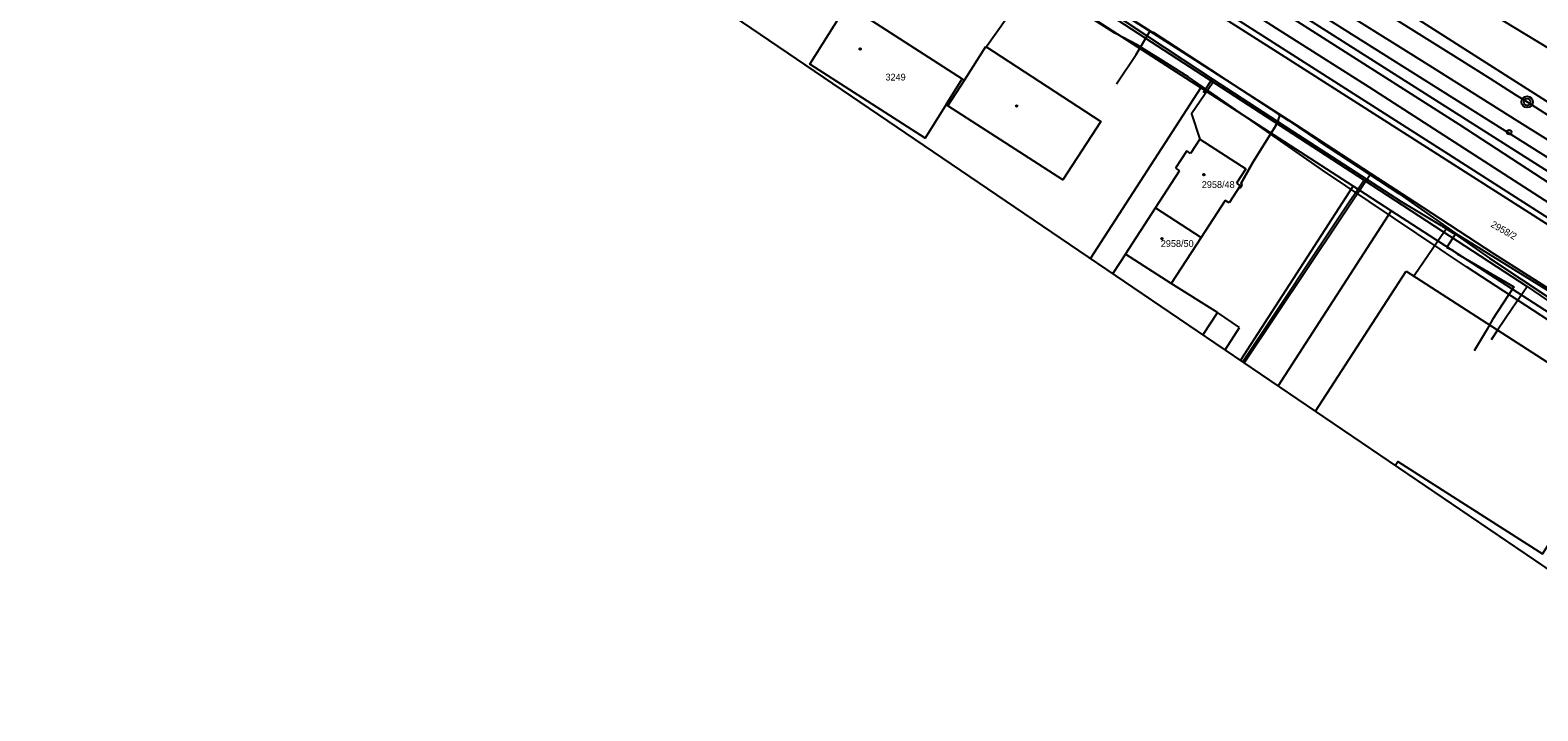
# Model space of a CAD drawing. Extents: x -621145 to -620110, y -1122807 to -1121971.
# Drawn here: x -620961 to -620628.4, y -1122600.4 to -1122450.2 of the extents above; entities that cross this region are included whole.
import ezdxf

# ---------------------------------------------------------------- set-up
doc = ezdxf.new("R2010")
doc.units = 0
for name, color, linetype in [('060601_EOV', 7, 'Continuous'), ('060604_ROZVODY_SEE', 7, 'Continuous'), ('CETIN', 7, 'Continuous'), ('GasNet', 7, 'Continuous'), ('itself', 7, 'Continuous'), ('PS 06-14-01_trasa_sdělovací_nové', 7, 'Continuous'), ('RÁMY', 7, 'Continuous'), ('SEE', 7, 'Continuous'), ('SSZT', 7, 'Continuous'), ('VAS stoka', 7, 'Continuous'), ('VAS vodovod', 7, 'Continuous'), ('Vrstva 1', 7, 'Continuous'), ('Vrstva 53', 7, 'Continuous'), ('Vrstva 55', 7, 'Continuous'), ('Vrstva 56', 7, 'Continuous'), ('Vrstva 57', 7, 'Continuous'), ('Vrstva 62', 7, 'Continuous'), ('Vrstva 7', 7, 'Continuous')]:
    doc.layers.add(name, color=color, linetype=linetype)

msp = doc.modelspace()

# ---------------------------------------------------------------- linework, layer by layer
at = {"layer": '060601_EOV'}
msp.add_lwpolyline([(-620599.21, -1122483.22), (-620683.52, -1122429.44), (-620756.33, -1122383.52), (-620765.8, -1122398.39), (-620784.65, -1122386.39), (-620822.22, -1122362.42), (-620817.53, -1122355.08), (-620826.41, -1122348.08), (-620839.92, -1122337.94), (-620848.84, -1122332), (-620848.83, -1122331.99)], dxfattribs=at)
at = {"layer": '060604_ROZVODY_SEE'}
msp.add_lwpolyline([(-620443.53, -1122595), (-620456.11, -1122587.12), (-620447.82, -1122572.96), (-620450.95, -1122571.45), (-620470.59, -1122561.48), (-620499.61, -1122545.57), (-620522.04, -1122531.47), (-620538.89, -1122521.21), (-620599.21, -1122483.22), (-620683.52, -1122429.44), (-620756.33, -1122383.52), (-620765.8, -1122398.39)], dxfattribs=at)
at = {"layer": 'CETIN'}
for points in [[(-620825.92, -1122405.87), (-620824.51, -1122406.99), (-620818.94, -1122399.06), (-620813.77, -1122391.56), (-620811.94, -1122388.94), (-620806.05, -1122392.88), (-620797.93, -1122398.39), (-620788.82, -1122404.57), (-620785.51, -1122405.86), (-620781.04, -1122408.44), (-620779.59, -1122408.85), (-620776.1, -1122410.97), (-620774.86, -1122411.81), (-620766.93, -1122416.76), (-620729.54, -1122440.11), (-620722.4, -1122445), (-620713.88, -1122450.37)], [(-620721.34, -1122462.04), (-620716.98, -1122455.59), (-620713.88, -1122450.37)], [(-620716.98, -1122455.59), (-620713.88, -1122450.37)], [(-620713.88, -1122450.37), (-620713.18, -1122450.73), (-620698.82, -1122460.09), (-620685.49, -1122468.76)], [(-620698.82, -1122460.09), (-620713.18, -1122450.73)], [(-620694.25, -1122484.84), (-620694.04, -1122484.98), (-620693.69, -1122484.45), (-620693.79, -1122484), (-620691.17, -1122479.25), (-620686.25, -1122471.41), (-620685.67, -1122470.12), (-620685.31, -1122469.14), (-620685.49, -1122468.76)], [(-620685.67, -1122470.12), (-620686.25, -1122471.41), (-620691.17, -1122479.25), (-620693.79, -1122484), (-620693.69, -1122484.45)], [(-620685.49, -1122468.76), (-620683.38, -1122470.13), (-620676.74, -1122474.66), (-620659.07, -1122486.24), (-620646.43, -1122495.05)], [(-620648.44, -1122498.16), (-620646.43, -1122495.05)], [(-620648.44, -1122498.16), (-620646.43, -1122495.05)], [(-620646.43, -1122495.05), (-620612.92, -1122515.84), (-620612.23, -1122516.26), (-620607.1, -1122519.79), (-620583.87, -1122535.51), (-620565.48, -1122548.17), (-620561.56, -1122551.58), (-620557.36, -1122556.05), (-620552.9, -1122562.72), (-620546.13, -1122574.35), (-620544.03, -1122578.53)], [(-620648.44, -1122498.16), (-620647.38, -1122498.61), (-620646.14, -1122499.59)], [(-620648.44, -1122498.16), (-620647.38, -1122498.61), (-620646.14, -1122499.59), (-620633.65, -1122506.89), (-620638.34, -1122514.06), (-620639.54, -1122516.17), (-620642.38, -1122521.01)], [(-620646.14, -1122499.59), (-620633.65, -1122506.89)], [(-620633.65, -1122506.89), (-620638.34, -1122514.06)], [(-620638.34, -1122514.06), (-620639.54, -1122516.17), (-620642.38, -1122521.01)]]:
    msp.add_lwpolyline(points, dxfattribs=at)
at = {"layer": 'GasNet'}
for points in [[(-620782.63, -1122409.86), (-620782.01, -1122410.24), (-620780.25, -1122411.07), (-620777.02, -1122412.94), (-620768.84, -1122416.49), (-620765.93, -1122417.88), (-620758.63, -1122422.59), (-620737.62, -1122436.24), (-620727.26, -1122442.97), (-620706.73, -1122456.7), (-620700.22, -1122460.96), (-620682.51, -1122472.52), (-620658.5, -1122488), (-620649.67, -1122493.31), (-620649.45, -1122493.45), (-620648.52, -1122494.04), (-620647.09, -1122494.92), (-620646.9, -1122495.04), (-620639.06, -1122500.54), (-620610.88, -1122519.2)], [(-620700.22, -1122460.96), (-620702.23, -1122464.06)], [(-620648.52, -1122494.04), (-620649.59, -1122495.62), (-620655.51, -1122504.17)], [(-620655.51, -1122504.17), (-620655.67, -1122504.4), (-620655.88, -1122504.7)]]:
    msp.add_lwpolyline(points, dxfattribs=at)
at = {"layer": 'itself'}
msp.add_lwpolyline([(-620616.25, -1122520.59), (-620644.13, -1122502.42), (-620648.74, -1122499.33), (-620649.95, -1122498.54), (-620675.91, -1122481.07), (-620699.14, -1122464.9), (-620705.51, -1122460.51), (-620711.67, -1122456.57), (-620715.75, -1122454.11), (-620716.79, -1122453.45), (-620721.67, -1122450.84), (-620745.77, -1122435.49)], dxfattribs=at)
at = {"layer": 'PS 06-14-01_trasa_sdělovací_nové'}
msp.add_lwpolyline([(-620538.89, -1122521.21), (-620538.89, -1122521.21), (-620599.21, -1122483.22), (-620683.52, -1122429.44), (-620756.33, -1122383.52), (-620761.98, -1122392.4), (-620753.37, -1122398.54), (-620735.26, -1122410.11), (-620735.26, -1122410.11)], dxfattribs=at)
at = {"layer": 'RÁMY'}
for points in [[(-621061.56, -1122093.92), (-620192.94, -1122683.83), (-620276.37, -1122806.68), (-621144.99, -1122216.77)], [(-620887.83, -1122211.9), (-620192.94, -1122683.83), (-620276.37, -1122806.68), (-620971.26, -1122334.75)]]:
    msp.add_lwpolyline(points, close=True, dxfattribs=at)
at = {"layer": 'SEE'}
msp.add_lwpolyline([(-620611.37, -1122497.7), (-620665.57, -1122462.75), (-620686.03, -1122449.83), (-620727.54, -1122423.18), (-620794.51, -1122379.86), (-620815.52, -1122356.95), (-620832.17, -1122344.66), (-620847.81, -1122332.59), (-620908.26, -1122294.69)], dxfattribs=at)
at = {"layer": 'SSZT'}
msp.add_lwpolyline([(-620879.24, -1122313.32), (-620842.99, -1122336.61), (-620835.05, -1122343.25), (-620812.66, -1122358.95), (-620764.9, -1122389.75), (-620688.59, -1122438.97), (-620596.98, -1122496.73), (-620576.74, -1122509.48), (-620506.75, -1122556.12), (-620447.29, -1122593.62), (-620363.27, -1122647.56), (-620313.97, -1122679.22), (-620306.51, -1122669.29), (-620273.14, -1122696.27), (-620258.42, -1122709.14), (-620248.07, -1122696.09)], dxfattribs=at)
at = {"layer": 'VAS stoka'}
msp.add_line((-620693.16, -1122523.62), (-620665.23, -1122481.83), dxfattribs=at)
msp.add_lwpolyline([(-620781.72, -1122408.87), (-620776.69, -1122412.14), (-620774.2, -1122412.02), (-620772.21, -1122412.95), (-620766.77, -1122415.95), (-620758.11, -1122421.89), (-620737.16, -1122435.39), (-620726.71, -1122442.22), (-620705.9, -1122455.54), (-620681.71, -1122471.08), (-620665.23, -1122481.83), (-620655.61, -1122488.12), (-620638.12, -1122499.53), (-620609.99, -1122517.38), (-620585.88, -1122533.44), (-620564.23, -1122548.6), (-620546.83, -1122572.05), (-620541.25, -1122582.33), (-620541.87, -1122584.42), (-620543.53, -1122584.85), (-620544.25, -1122585.03)], dxfattribs=at)
at = {"layer": 'VAS vodovod'}
for points in [[(-620783.05, -1122410.36), (-620779.49, -1122412.44), (-620776.82, -1122413.57), (-620766.15, -1122419), (-620759.23, -1122423.16), (-620738.05, -1122436.88), (-620666.7, -1122483.31), (-620630.69, -1122506.76), (-620611.44, -1122519.95), (-620587.32, -1122536.52), (-620566.14, -1122551.51), (-620558.22, -1122559.71), (-620551.85, -1122569.08), (-620547.83, -1122576.32), (-620546.15, -1122586.98), (-620546.1, -1122587.26)], [(-620738.05, -1122436.88), (-620738.12, -1122437.06), (-620750.23, -1122454.2)], [(-620699.97, -1122461.66), (-620704.79, -1122468.67), (-620702.93, -1122474.27)], [(-620666.7, -1122483.31), (-620668.33, -1122485.75), (-620669.97, -1122488.2), (-620693.49, -1122523.4)], [(-620630.69, -1122506.76), (-620630.78, -1122506.91), (-620634.04, -1122511.65), (-620637.29, -1122516.39), (-620638.69, -1122518.58)]]:
    msp.add_lwpolyline(points, dxfattribs=at)
at = {"layer": 'Vrstva 1'}
for points in [[(-620851.64, -1122327.08), (-620840.38, -1122334.59), (-620831.19, -1122341.26), (-620824.9, -1122346.12), (-620811.35, -1122356.78), (-620800.85, -1122364.55), (-620800.09, -1122365.07), (-620796.17, -1122367.69), (-620795.02, -1122368.44), (-620786.31, -1122373.93), (-620764.42, -1122387.67), (-620747.63, -1122398.19), (-620733.73, -1122406.89), (-620718.35, -1122416.52), (-620703.01, -1122426.15), (-620686.98, -1122436.2), (-620670.85, -1122446.34), (-620652.24, -1122458.03), (-620632.99, -1122470.12), (-620616.99, -1122480.17)], [(-620538.89, -1122521.21), (-620599.21, -1122483.22), (-620683.52, -1122429.44), (-620747.38, -1122389.13), (-620756.33, -1122383.52)], [(-620659.94, -1122447.67), (-620652.83, -1122452.14), (-620645.8, -1122456.55), (-620638.91, -1122460.88), (-620633.12, -1122464.53), (-620630.72, -1122466.04), (-620624.36, -1122470.05)], [(-620659.94, -1122447.67), (-620652.83, -1122452.14), (-620645.8, -1122456.55), (-620638.91, -1122460.88), (-620633.12, -1122464.53), (-620630.72, -1122466.04), (-620624.36, -1122470.05)]]:
    msp.add_lwpolyline(points, dxfattribs=at)
at = {"layer": 'Vrstva 53'}
for p, q in [((-620638.48, -1122446.57), (-620552.09, -1122499.2)), ((-620545.92, -1122532.26), (-620679.51, -1122447.56))]:
    msp.add_line(p, q, dxfattribs=at)
at = {"layer": 'Vrstva 55'}
for p, q in [((-620684.91, -1122455.63), (-620825.92, -1122365.89)), ((-620645.72, -1122471.03), (-620807.67, -1122367.84)), ((-620702.74, -1122462.95), (-620757.34, -1122427.68)), ((-620638.48, -1122446.57), (-620552.09, -1122499.2)), ((-620545.92, -1122532.26), (-620679.51, -1122447.56)), ((-620754.9, -1122461.23), (-620750.13, -1122453.84)), ((-620557.45, -1122536.96), (-620684.91, -1122455.63)), ((-620755.36, -1122460.94), (-620754.9, -1122461.23)), ((-620727.06, -1122500.6), (-620702.74, -1122462.95)), ((-620669.14, -1122484.66), (-620702.74, -1122462.95)), ((-620758.55, -1122466.88), (-620758.93, -1122466.63)), ((-620587.17, -1122509.18), (-620645.72, -1122471.03)), ((-620705.81, -1122476.87), (-620708.28, -1122480.69)), ((-620704.97, -1122477.41), (-620705.81, -1122476.87)), ((-620702.93, -1122474.27), (-620704.97, -1122477.41)), ((-620702.93, -1122474.27), (-620692.81, -1122480.83)), ((-620708.28, -1122480.69), (-620707.44, -1122481.23)), ((-620712.73, -1122489.39), (-620707.44, -1122481.23)), ((-620692.81, -1122480.83), (-620694.86, -1122483.99)), ((-620694.86, -1122483.99), (-620694.01, -1122484.54)), ((-620694.01, -1122484.54), (-620696.48, -1122488.34)), ((-620693.96, -1122523.08), (-620669.14, -1122484.66)), ((-620660.74, -1122490.09), (-620669.14, -1122484.66)), ((-620719.36, -1122499.62), (-620712.73, -1122489.39)), ((-620712.73, -1122489.39), (-620702.63, -1122495.93)), ((-620697.33, -1122487.79), (-620702.63, -1122495.93)), ((-620696.48, -1122488.34), (-620697.33, -1122487.79)), ((-620660.74, -1122490.09), (-620685.68, -1122528.7)), ((-620576.58, -1122544.45), (-620660.74, -1122490.09)), ((-620702.63, -1122495.93), (-620709.28, -1122506.15)), ((-620719.36, -1122499.62), (-620722.14, -1122503.94)), ((-620677.41, -1122534.31), (-620657.43, -1122503.38)), ((-620657.43, -1122503.38), (-620581.67, -1122552.32)), ((-620699.07, -1122512.52), (-620709.28, -1122506.15)), ((-620694.2, -1122515.81), (-620699.07, -1122512.52)), ((-620697.39, -1122520.75), (-620694.2, -1122515.81))]:
    msp.add_line(p, q, dxfattribs=at)
for points in [[(-620758.93, -1122466.63), (-620763.57, -1122474.01), (-620789, -1122457.71), (-620780.78, -1122444.6), (-620755.36, -1122460.94)], [(-620750.13, -1122453.84), (-620724.79, -1122470.34), (-620733.19, -1122483.27), (-620758.55, -1122466.88)], [(-620659.82, -1122546.26), (-620659.27, -1122545.41), (-620652.1, -1122549.99), (-620627.31, -1122565.82), (-620622.82, -1122558.97), (-620611.91, -1122565.95), (-620616.39, -1122572.84)]]:
    msp.add_lwpolyline(points, dxfattribs=at)
at = {"layer": 'Vrstva 56'}
for p, q in [((-620810.36, -1122373.73), (-620648.08, -1122477.56)), ((-620758.93, -1122466.63), (-620755.36, -1122460.94)), ((-620758.55, -1122466.88), (-620754.9, -1122461.23)), ((-620648.08, -1122477.56), (-620625, -1122492.37)), ((-620709.28, -1122506.15), (-620719.36, -1122499.62)), ((-620699.07, -1122512.52), (-620702.26, -1122517.44))]:
    msp.add_line(p, q, dxfattribs=at)
at = {"layer": 'Vrstva 57'}
for centre in [(-620777.9, -1122454.36), (-620743.34, -1122466.95), (-620702.05, -1122482.08), (-620711.29, -1122496.23)]:
    msp.add_circle(centre, 0.175, dxfattribs=at)
at = {"layer": 'Vrstva 62'}
for p, q in [((-620651.85, -1122457.42), (-620651.85, -1122457.42)), ((-620652.64, -1122458.63), (-620652.64, -1122458.63)), ((-620633.37, -1122470.75), (-620633.37, -1122470.75)), ((-620632.61, -1122469.5), (-620632.61, -1122469.5))]:
    msp.add_line(p, q, dxfattribs=at)
at = {"layer": 'Vrstva 7'}
msp.add_line((-620634.74, -1122472.68), (-620634.66, -1122472.73), dxfattribs=at)
msp.add_line((-620634.74, -1122472.68), (-620634.66, -1122472.73), dxfattribs=at)
for centre, radius in [((-620630.72, -1122466.04), 1.25), ((-620630.72, -1122466.04), 1.25), ((-620630.72, -1122466.04), 0.752), ((-620630.72, -1122466.04), 0.752), ((-620634.7, -1122472.71), 0.5), ((-620634.7, -1122472.71), 0.5)]:
    msp.add_circle(centre, radius, dxfattribs=at)

# ---------------------------------------------------------------- texts
at = {"layer": 'Vrstva 57'}
for s, p in [('3249', (-620772.31, -1122461.31)), ('2958/48', (-620702.51, -1122485.03)), ('2958/50', (-620711.56, -1122498.05))]:
    msp.add_text(s, height=1.5, dxfattribs=at).set_placement(p)
msp.add_text('2958/2', height=1.5, rotation=330.3, dxfattribs=at).set_placement((-620638.9, -1122493.5))

doc.saveas('drawing.dxf')
